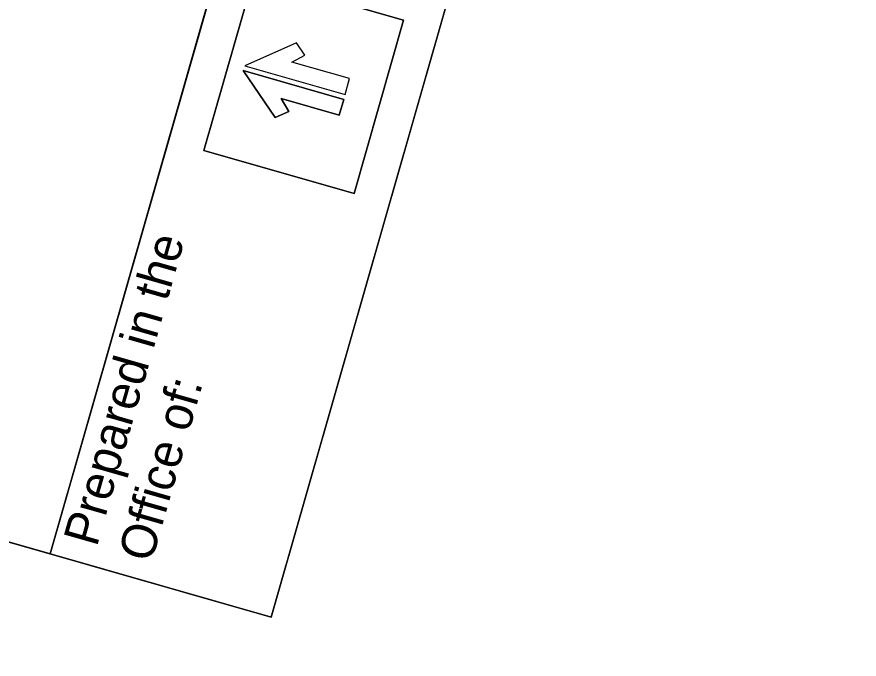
# Model space of a CAD drawing. Extents: x 2096976 to 2098492, y 681809 to 689636.
# Drawn here: x 2097541.4 to 2097637.6, y 689367.6 to 689441 of the extents above; entities that cross this region are included whole.
import ezdxf

# ---------------------------------------------------------------- set-up
doc = ezdxf.new("R2010")
doc.units = 0
for name, color, linetype in [('Scratch_Level_6', 7, 'Continuous'), ('Sheet Block Title CELL', 7, 'Continuous'), ('Sheet Plan CELL', 7, 'Continuous')]:
    doc.layers.add(name, color=color, linetype=linetype)

msp = doc.modelspace()

# ---------------------------------------------------------------- linework, layer by layer
at = {"layer": 'Scratch_Level_6'}
msp.add_lwpolyline([(2098102.099, 688055.095), (2097347.726, 688084.027), (2097057.832, 688167.011), (2097360.525, 689224.432), (2097385.767, 689217.206), (2097440.821, 689409.53), (2097570.413, 689372.443), (2097625.464, 689564.757), (2098465.421, 689324.313)], close=True, dxfattribs=at)
at = {"layer": 'Sheet Block Title CELL'}
for points in [[(2097545.171, 689379.669), (2097600.227, 689572.002), (2097625.47, 689564.776), (2097570.413, 689372.443)], [(2097562.728, 689425.719), (2097568.386, 689445.482), (2097585.539, 689440.572), (2097579.882, 689420.808)], [(2097567.394, 689435.387), (2097578.864, 689432.103), (2097579.381, 689433.91), (2097572.765, 689435.804), (2097574.27, 689436.584), (2097573.315, 689437.996)]]:
    msp.add_lwpolyline(points, close=True, dxfattribs=at)
for points in [[(2097568.386, 689445.482), (2097562.728, 689425.719), (2097579.882, 689420.808), (2097585.539, 689440.572), (2097568.386, 689445.482)], [(2097567.394, 689435.387), (2097578.864, 689432.103), (2097579.381, 689433.91), (2097572.765, 689435.804), (2097574.27, 689436.584), (2097573.315, 689437.996), (2097567.394, 689435.387)], [(2097567.235, 689434.83), (2097578.705, 689431.547), (2097578.187, 689429.741), (2097571.572, 689431.634), (2097572.436, 689430.176), (2097570.878, 689429.484), (2097567.235, 689434.83)], [(2097570.878, 689429.484), (2097572.436, 689430.176), (2097571.572, 689431.634), (2097578.187, 689429.741), (2097578.705, 689431.547), (2097567.235, 689434.83), (2097570.878, 689429.484)]]:
    msp.add_lwpolyline(points, dxfattribs=at)
at = {"layer": 'Sheet Plan CELL'}
for points in [[(2098052.613, 687882.222), (2097043.175, 688171.154), (2097400.899, 689420.955), (2097545.171, 689379.669), (2097600.234, 689571.979), (2098465.421, 689324.313)], [(2097437.023, 689410.614), (2097464.557, 689506.801), (2097572.725, 689475.837), (2097545.171, 689379.669)]]:
    msp.add_lwpolyline(points, close=True, dxfattribs=at)

# ---------------------------------------------------------------- texts
at = {"layer": 'Sheet Block Title CELL'}
for s, height, p in [('Prepared in the ', 4.00116, (2097550.498, 689380.352)), ('Office of:', 4.0012, (2097556.749, 689378.562))]:
    msp.add_text(s, height=height, rotation=74.02589, dxfattribs=at).set_placement(p)

doc.saveas('drawing.dxf')
